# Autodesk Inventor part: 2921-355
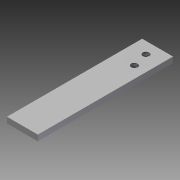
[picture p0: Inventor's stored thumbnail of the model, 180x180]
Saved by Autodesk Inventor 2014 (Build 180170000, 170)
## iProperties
Company: NHTSA/VRTC
Created: 2012-12
Part Number: 2921-355
Material: Steel, Mild
Document SubType Name: Modeling
Designer: Mike Vanvoorhis
Density: 7.86 g/cm^3
Mass: 832.072 g
Surface Area: 280.637 cm^2
Volume: 105.862 cm^3
Project: CHILD SIDE IMPACT SLED
Description: LOWER ANCHOR BELT ATTACHMENT PLATE
Appearance: Steel
Stock Number: BAR 50.8 (2") x 9.5 (3/8") x 222.3 (8 3/4")
Author: Dave Walker
Title: Lower Anchor Belt Attachment Plate
Subject: Child Side Impact Sled
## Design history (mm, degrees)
sketch "Sketch1"
  geometry: L1 (0, 0)-(50.8, 0); L2 (50.8, 0)-(50.8, 9.525); L3 (50.8, 9.525)-(0, 9.525); L4 (0, 9.525)-(0, 0)
  constraints: 8 end point, 2 parallel, 1 horizontal, 1 perpendicular
  dimensions: "d0" = 50.8 distance of L3.end L2.end; "d1" = 9.525 distance of L2.end L1.end
extrude "Extrusion1" new body sketch "Sketch1" distance "d2" = 222.25; taper "d3" = 0 deg
sketch "Sketch2"
  geometry: L1 (50.8, 222.25)-(0, 222.25) reference; L2 (50.8, 0)-(50.8, 222.25) reference; L3 (25.4, 222.25)-(25.4, 203.2)
  constraints: 2 end point, 1 midpoint, 1 parallel
  dimensions: "d4" = 19.05 distance of L3.start L3.end
hole "Hole1" sketch "Sketch2" at (25.4, 203.2) diameter "d5" = 10.5918; stored, may be unused: countersink angle "d9" = 82 deg, drill point angle "d11" = 118 deg; dims "d6" = 19.05, "d7" = 9.525, "d8" = 6.35, "d10" = 25.4
sketch "Sketch3"
  geometry: L1 (0, 0)-(0, 222.25) reference; L2 (50.8, 0)-(50.8, 222.25) reference; L3 (50.8, 177.8)-(0, 177.8); L4 (50.8, 177.8)-(31.75, 177.8)
  constraints: 4 end point, 3 point on line, 1 perpendicular
  dimensions: "d12" = 177.8 distance of L2.start L3.start; "d13" = 19.05 distance of L3.start L4.end
hole "Hole2" sketch "Sketch3" at (31.75, 177.8) diameter "d14" = 10.5918; stored, may be unused: countersink angle "d18" = 82 deg, drill point angle "d20" = 118 deg; dims "d15" = 19.05, "d16" = 9.525, "d17" = 6.35, "d19" = 25.4
body "Solid1"
